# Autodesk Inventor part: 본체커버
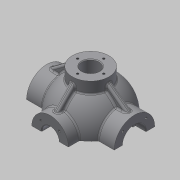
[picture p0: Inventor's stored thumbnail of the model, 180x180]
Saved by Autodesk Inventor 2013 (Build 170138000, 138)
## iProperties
Created: 2015-12
Part Number: 본체커버
Material: 알루미늄 6061
Document SubType Name: Modeling
Designer: mduedu
Density: 2.71 g/cm^3
Mass: 589.734 g
Surface Area: 460.056 cm^2
Volume: 217.614 cm^3
Author: mduedu
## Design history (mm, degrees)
sketch "스케치1"
  geometry: L1 (-53, 0)-(53, 0); A1 r 53 centre (0, 0) between (53, 0) and (-53, 0); 2 further points
  constraints: 2 coincident, 2 end point, 2 point on circle, 1 centre point, 1 horizontal, 1 midpoint
  dimensions: "d0" = 53 radius of A1
revolve "회전1" sketch "스케치1" stored, may be unused: angle "d2" = 90 deg
feature "쉘1" dims "d11" = 10
node "작업 평면1"
sketch "스케치2"
  geometry: C1 r 31 at (0, 0); 1 further point
  constraints: 1 centre point, 1 coincident
  dimensions: "d4" = 62 diameter of C1
extrude "돌출1" join sketch "스케치2" stored distance "d5" = 10; taper "d6" = 0 deg
node "작업 평면2"
sketch "스케치3"
  geometry: C1 r 28 at (0, 0); 1 further point
  constraints: 1 centre point, 1 coincident
  dimensions: "d8" = 56 diameter of C1
extrude "돌출2" join sketch "스케치3" stored distance "d9" = 10; taper "d10" = 0 deg
hole "구멍1" diameter "d14" = 35; stored, may be unused: countersink angle "d18" = 90 deg, drill point angle "d20" = 0 deg; dims "d12" = 10, "d13" = 10, "d15" = 6, "d16" = 4, "d17" = 2, "d19" = 16
hole "구멍2" diameter "d23" = 27; stored, may be unused: countersink angle "d27" = 90 deg, drill point angle "d29" = 0 deg; dims "d21" = 10, "d22" = 10, "d24" = 6, "d25" = 4, "d26" = 2, "d28" = 16
fillet "모깎기1" dims "d30" = 0.3
hole "구멍3" diameter "d33" = 26; stored, may be unused: countersink angle "d37" = 90 deg, drill point angle "d39" = 0 deg; dims "d31" = 10, "d32" = 10, "d34" = 6, "d35" = 4, "d36" = 2, "d38" = 16
chamfer "모따기1" distance "d40" = 1; stored, may be unused: second distance "d41" = 2, angle "d42" = 45 deg
sketch "스케치4"
  geometry: L1 (0, 0)-(0, -25); L2 (0, 0)-(-17.678, -17.678); A1 r 25 centre (0, 0) between (-17.678, -17.678) and (0, -25); 1 further point
  constraints: 4 end point, 2 point on circle, 1 centre point, 1 coincident, 1 vertical
  dimensions: "d43" = 50 diameter of A1; "d47" = 45 deg angle of L1 L2
hole "구멍4" sketch "스케치4" at (-17.678, -17.678) diameter "d49" = 3.242; stored, may be unused: countersink angle "d53" = 90 deg, drill point angle "d55" = 118 deg; dims "d50" = 11, "d51" = 4, "d52" = 2, "d54" = 13
sketch "스케치5"
  geometry: L1 (0, 0)-(0, -20); L2 (0, 0)-(-14.142, -14.142); A1 r 20 centre (0, 0) between (0, -20) and (-14.142, -14.142); 2 further points
  constraints: 4 end point, 2 coincident, 2 point on circle, 1 centre point, 1 vertical
  dimensions: "d59" = 40 diameter of A1; "d65" = 45 deg angle of L1 L2
hole "구멍5" sketch "스케치5" at (-14.142, -14.142) diameter "d67" = 3.242; stored, may be unused: countersink angle "d71" = 90 deg, drill point angle "d73" = 118 deg; dims "d68" = 8, "d69" = 4, "d70" = 2, "d72" = 10
node "작업 평면3"
sketch "스케치6"
  geometry: C1 r 65 at (0, 0); 1 further point
  constraints: 1 centre point, 1 coincident
  dimensions: "d78" = 130 diameter of C1
extrude "돌출3" join sketch "스케치6" distance "d80" = 10; taper "d81" = 0 deg
sketch "스케치7"
  geometry: C1 r 20 at (0, 0); 1 further point
  constraints: 1 centre point, 1 coincident
  dimensions: "d82" = 40 diameter of C1
extrude "돌출4" join sketch "스케치7" stored distance "d84" = 10; taper "d85" = 0 deg
sketch "스케치8"
  geometry: 2 further points
  constraints: 1 coincident
hole "구멍6" sketch "스케치8" at (0, 0) diameter "d86" = 20; stored, may be unused: countersink angle "d90" = 90 deg, drill point angle "d92" = 118 deg; dims "d87" = 7, "d88" = 40, "d89" = 5, "d91" = 10
fillet "모깎기2" dims "d93" = 0.3
sketch "스케치9"
  geometry: L1 (65, -75)-(-65, -75) reference; L2 (-45, -75)-(-38.245, -36.692); A1 r 53 centre (0, 0) between (42.988, 31) and (42.988, -31) reference; 1 further point
  constraints: 2 end point, 1 point on circle, 1 point on line
  dimensions: "d94" = 45 horizontal distance of L2.start point (0, 0); "d95" = 80 deg angle of L2 L1
feature "리브1" sketch "스케치9" dims "d96" = 1, "d97" = 8, "d98" = 0, "d99" = 0, "d100" = 1, "d101" = 1
sketch "스케치10"
  geometry: L1 (0, 0)-(0, -55); L2 (0, 0)-(-38.891, -38.891); A1 r 55 centre (0, 0) between (0, -55) and (-38.891, -38.891); 2 further points
  constraints: 4 end point, 2 coincident, 2 point on circle, 1 centre point, 1 vertical
  dimensions: "d105" = 110 diameter of A1; "d107" = 45 deg angle of L1 L2
hole "구멍7" sketch "스케치10" at (-38.891, -38.891) diameter "d109" = 10; stored, may be unused: countersink angle "d113" = 90 deg, drill point angle "d115" = 118 deg; dims "d110" = 7, "d111" = 40, "d112" = 5, "d114" = 10
fillet "모깎기3" dims "d120" = 3
fillet "모깎기4" dims "d121" = 3, "d122" = 3
fillet "모깎기5" dims "d123" = 3
fillet "모깎기6" dims "d124" = 3
sketch "스케치11"
  geometry: C1 r 5 at (-38.891, 38.891) reference; C2 r 5 at (38.891, 38.891) reference; C3 r 5 at (38.891, -38.891) reference; C4 r 5 at (-38.891, -38.891) reference; C5 r 20 at (0, 0) reference; C6 r 65 at (0, 0) reference; 1 further point
  constraints: 3 other
feature "엠보싱1" sketch "스케치11" dims "d125" = 0.5, "d126" = 0
sketch "스케치12"
  geometry: L1 (0, 100)-(0, -100); L2 (0, 100)-(-150, 100); L3 (-150, 100)-(-150, -100); L4 (-150, -100)-(0, -100); 2 further points
  constraints: 8 end point, 3 perpendicular, 1 coincident, 1 midpoint, 1 vertical
  dimensions: "d127" = 200 distance of L2.end L3.end; "d129" = 150 distance of L3.end L1.end
extrude "돌출5" cut sketch "스케치12" stored distance "d130" = 10; taper "d131" = 0 deg
sketch "스케치13"
  geometry: C1 r 7 at (0, -53); A1 r 53 centre (0, 0) between (-42.113, -32.179) and (42.113, -32.179) reference; 1 further point
  constraints: 1 centre point, 1 point on circle
  dimensions: "d132" = 14 diameter of C1
extrude "돌출6" join sketch "스케치13" distance "d133" = 5; taper "d134" = 0 deg
sketch "스케치14"
  geometry: C1 r 7 at (0, 0) reference; 1 further point
extrude "돌출7" cut sketch "스케치14" stored distance "d135" = 5; taper "d136" = 0 deg
sketch "스케치15"
  geometry: C1 r 2.25 at (0, 53); A1 r 7 centre (0, 53) between (6.965, 52.302) and (-6.965, 52.302) reference; 1 further point
  constraints: 1 centre point, 1 coincident
  dimensions: "d139" = 4.5 diameter of C1
extrude "돌출8" cut sketch "스케치15" stored distance "d141" = 5; taper "d142" = 0 deg
fillet "모깎기7" dims "d143" = 3
fillet "모깎기8" dims "d144" = 1
fillet "모깎기9" dims "d145" = 1
fillet "모깎기10" dims "d146" = 1
node "작업 평면4"
sketch "스케치16"
  geometry: C1 r 28 at (0, 0); 1 further point
  constraints: 1 centre point, 1 coincident
  dimensions: "d148" = 56 diameter of C1
extrude "돌출9" join sketch "스케치16" stored distance "d150" = 5; taper "d151" = 0 deg
hole "구멍8" diameter "d154" = 26; stored, may be unused: countersink angle "d158" = 90 deg, drill point angle "d160" = 118 deg; dims "d152" = 10, "d153" = 10, "d155" = 6, "d156" = 4, "d157" = 2, "d159" = 8
sketch "스케치17" dims "d161" = 40
  geometry: 3 further points
  constraints: 2 vertical alignment, 1 coincident, 2 other
hole "구멍9" sketch "스케치17" at (0, 20) diameter "d163" = 3.242; stored, may be unused: countersink angle "d167" = 90 deg, drill point angle "d169" = 118 deg; dims "d164" = 8, "d165" = 4, "d166" = 2, "d168" = 10
fillet "모깎기11" dims "d173" = 3
chamfer "모따기2" distance "d174" = 1; stored, may be unused: second distance "d175" = 2, angle "d176" = 45 deg
sketch "스케치18"
  geometry: L1 (28, 62)-(28, 46.637) reference; L2 (67, 31)-(44.497, 31) reference; L3 (28, 55)-(60, 31); L4 (-28, 62)-(28, 62) reference; L5 (67, 31)-(67, 0) reference; 1 further point
  constraints: 2 end point, 2 point on line
  dimensions: "d177" = 7 distance from line of L3.start L4; "d178" = 7 distance from line of L3.end L5
feature "리브2" sketch "스케치18" dims "d179" = 1, "d180" = 8, "d181" = 0, "d182" = 0, "d183" = 1, "d184" = 1
fillet "모깎기12" dims "d185" = 3
fillet "모깎기13" dims "d186" = 3
sketch "스케치19"
  geometry: L1 (62, 28)-(46.637, 28) reference; L2 (28, 62)-(28, 46.637) reference; L3 (55, 28)-(28, 55); L4 (0, 62)-(28, 62) reference; L5 (62, 28)-(62, -28) reference; 1 further point
  constraints: 2 end point, 2 point on line
  dimensions: "d187" = 7 distance from line of L3.end L4; "d188" = 7 distance from line of L3.start L5
feature "리브3" sketch "스케치19" dims "d189" = 1, "d190" = 8, "d191" = 0, "d192" = 0, "d193" = 1, "d194" = 1
fillet "모깎기14" dims "d195" = 3
fillet "모깎기15" dims "d196" = 3
node "솔리드1"
mirror "대칭1"
mirror "대칭2"
pattern_circular "원형 패턴1" dims angle "d57" = 360 deg
mirror "대칭3"
pattern_circular "원형 패턴2" dims angle "d75" = 360 deg
pattern_circular "원형 패턴3" dims angle "d103" = 360 deg
pattern_circular "원형 패턴4" dims angle "d118" = 360 deg
pattern_circular "원형 패턴5" dims angle "d171" = 360 deg
mirror "대칭4"
node "투영된 루프1"
other parameters: "d3" = 67, "d7" = 62, "d77" = -85, "d147" = 62
